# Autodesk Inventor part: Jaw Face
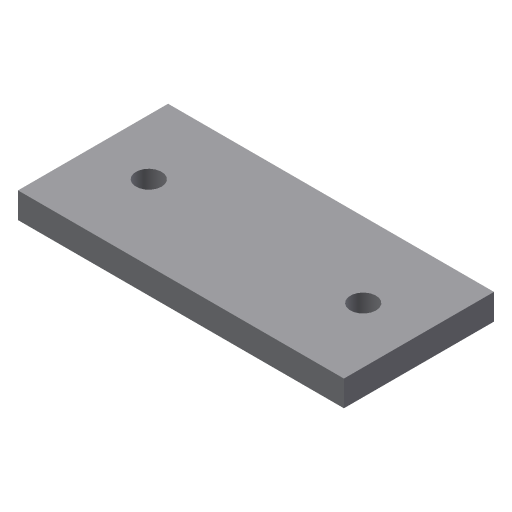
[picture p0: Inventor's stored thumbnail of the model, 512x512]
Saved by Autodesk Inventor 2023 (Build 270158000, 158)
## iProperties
Shininess: 77.0
Length Units: 11269
Angle Units: 11279
Time Units: 11290
Mass Units: 11283
Length Display Precision: 3
Angle Display Precision: 2
Compacted: True
Created: 2002-02
Part Number: Jaw Face
Document SubType Name: Modeling
Designer: ***
Density: 1 g/cm^3
Material: Generic
Appearance: Default
Density: 0.0
Volumn: 0.0
Area: 0.0
PropertySet Name: Model Information
Control State: 0
Master: False
Checked Out: False
Author: ***
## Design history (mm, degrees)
sketch "Sketch1"
  geometry: L1 (-79.661, -8.43)-(-3.661, -8.43); L2 (-3.661, -8.43)-(-3.661, -43.43); L3 (-3.661, -43.43)-(-79.661, -43.43); L4 (-79.661, -43.43)-(-79.661, -8.43); C1 r 3 at (-66.661, -25.93); C2 r 3 at (-16.661, -25.93)
  constraints: 8 end point, 2 centre point, 2 parallel, 1 equal radius, 1 horizontal, 1 perpendicular
  dimensions: "d0" = 76 distance of L2.end L3.end; "d1" = 6 diameter of C1; "d2" = 50 distance of C2.centre C1.centre; "d3" = 35 distance of L1.end L2.end; "d4" = 17.5 distance from line of L3 C2.centre; "d5" = 13 distance from line of L2 C2.centre; "d6" = 13 distance from line of L4 C1.centre
extrude "Extrusion1" new body sketch "Sketch1" stored distance "d7" = 6; taper "d8" = 0 deg
body "Solid1"
